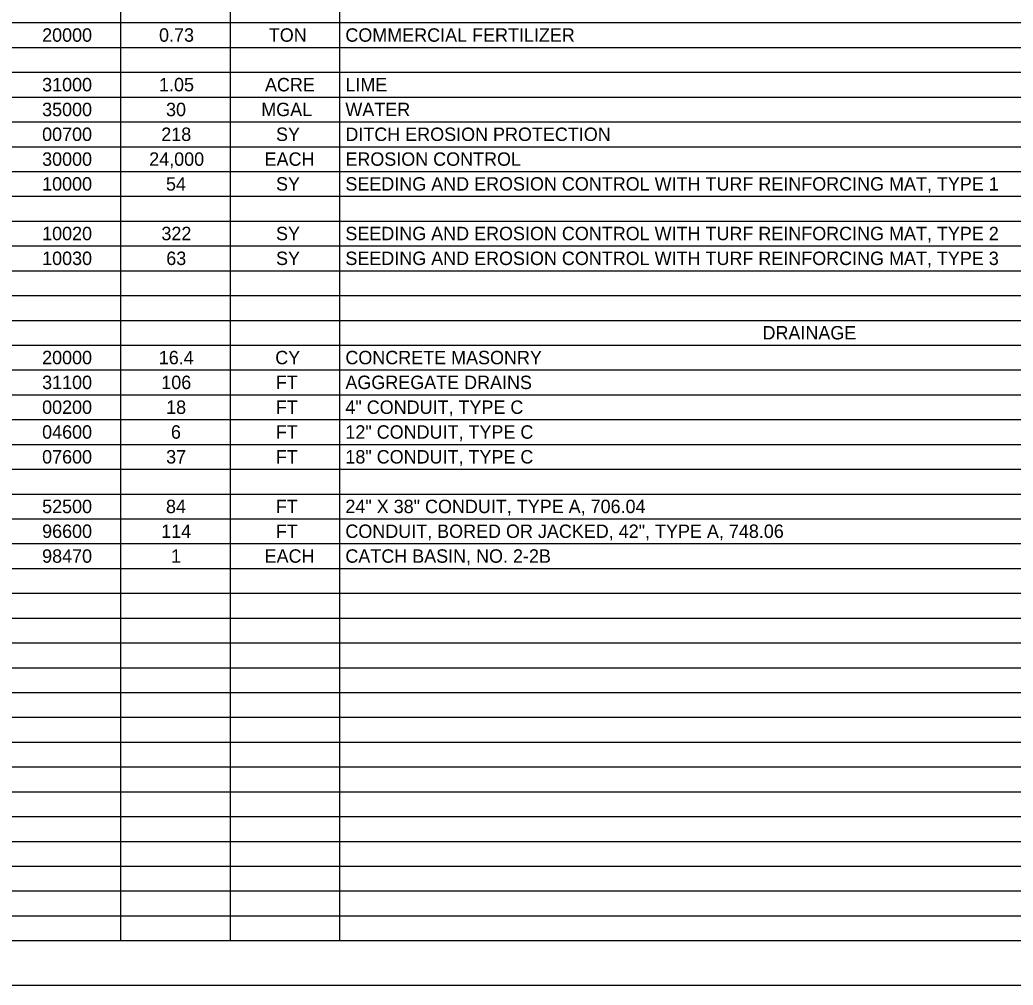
# Model space of a CAD drawing. Extents: x 0 to 1700, y 0 to 1100.
# Drawn here: x 845 to 1405, y 0 to 545 of the extents above; entities that cross this region are included whole.
import ezdxf

# ---------------------------------------------------------------- set-up
doc = ezdxf.new("R2010")
doc.units = 0
for name, color, linetype in [('SH_Border', 7, 'Continuous'), ('SH_Cut_Line', 7, 'Continuous'), ('SH_Text', 7, 'Continuous')]:
    doc.layers.add(name, color=color, linetype=linetype)

msp = doc.modelspace()

# ---------------------------------------------------------------- linework, layer by layer
at = {"layer": 'SH_Border'}
msp.add_lwpolyline([(75, 1075), (1675, 1075), (1675, 25), (75, 25)], close=True, dxfattribs=at)
at = {"layer": 'SH_Cut_Line'}
msp.add_lwpolyline([(0, 0), (1700, 0), (1700, 1100), (0, 1100)], close=True, dxfattribs=at)
at = {"layer": 'SH_Text'}
for p, q in [((901.73, 1075), (901.73, 25.12)), ((963.49, 1075), (963.49, 25.12)), ((1025.24, 1075), (1025.24, 25.12)), ((75, 543.06), (1600, 543.06)), ((75, 529.06), (1600, 529.06)), ((75, 515.06), (1600, 515.06)), ((75, 501.07), (1600, 501.07)), ((75, 487.07), (1600, 487.07)), ((75, 473.07), (1600, 473.07)), ((75, 459.07), (1600, 459.07)), ((75, 445.07), (1600, 445.07)), ((75, 431.07), (1600, 431.07)), ((75, 417.08), (1600, 417.08)), ((75, 403.08), (1600, 403.08)), ((75, 389.08), (1600, 389.08)), ((75, 375.08), (1600, 375.08)), ((75, 361.08), (1600, 361.08)), ((75, 347.08), (1600, 347.08)), ((75, 333.09), (1600, 333.09)), ((75, 319.09), (1600, 319.09)), ((75, 305.09), (1600, 305.09)), ((75, 291.09), (1600, 291.09)), ((75, 277.09), (1600, 277.09)), ((75, 263.09), (1600, 263.09)), ((75, 249.1), (1600, 249.1)), ((75, 235.1), (1600, 235.1)), ((75, 221.1), (1600, 221.1)), ((75, 207.1), (1600, 207.1)), ((75, 193.1), (1600, 193.1)), ((75, 179.1), (1600, 179.1)), ((75, 165.11), (1600, 165.11)), ((75, 151.11), (1600, 151.11)), ((75, 137.11), (1600, 137.11)), ((75, 123.11), (1600, 123.11)), ((75, 109.11), (1600, 109.11)), ((75, 95.11), (1600, 95.11)), ((75, 81.12), (1600, 81.12)), ((75, 67.12), (1600, 67.12)), ((75, 53.12), (1600, 53.12)), ((75, 39.12), (1600, 39.12)), ((75, 25.12), (1600, 25.12))]:
    msp.add_line(p, q, dxfattribs=at)

# ---------------------------------------------------------------- texts
for s, height, p in [('20000', 7.576, (857.43, 532.27)), ('0.73', 7.576, (923.41, 532.27)), ('TON', 7.576, (985.33, 532.27)), ('COMMERCIAL FERTILIZER', 7.5756, (1028.54, 532.27)), ('31000', 7.576, (857.43, 504.28)), ('1.05', 7.576, (923.4, 504.28)), ('ACRE', 7.576, (983.17, 504.28)), ('LIME', 7.576, (1028.54, 504.28)), ('35000', 7.576, (857.43, 490.28)), ('30', 7.576, (927.35, 490.28)), ('MGAL', 7.576, (981.06, 490.28)), ('WATER', 7.576, (1028.54, 490.28)), ('00700', 7.576, (857.43, 476.28)), ('218', 7.576, (924.67, 476.28)), ('SY', 7.576, (989.41, 476.28)), ('DITCH EROSION PROTECTION', 7.5756, (1028.54, 476.28)), ('30000', 7.576, (857.43, 462.28)), ('24,000', 7.576, (917.85, 462.28)), ('EACH', 7.576, (982.97, 462.28)), ('EROSION CONTROL', 7.5756, (1028.54, 462.28)), ('10000', 7.576, (857.43, 448.28)), ('54', 7.576, (927.32, 448.28)), ('SY', 7.576, (989.41, 448.28)), ('SEEDING AND EROSION CONTROL WITH TURF REINFORCING MAT, TYPE 1', 7.5756, (1028.54, 448.28)), ('10020', 7.576, (857.43, 420.29)), ('322', 7.576, (924.74, 420.29)), ('SY', 7.576, (989.41, 420.29)), ('SEEDING AND EROSION CONTROL WITH TURF REINFORCING MAT, TYPE 2', 7.5756, (1028.54, 420.29)), ('10030', 7.576, (857.43, 406.29)), ('63', 7.576, (927.49, 406.29)), ('SY', 7.576, (989.41, 406.29)), ('SEEDING AND EROSION CONTROL WITH TURF REINFORCING MAT, TYPE 3', 7.5756, (1028.54, 406.29)), ('DRAINAGE', 7.576, (1263.88, 364.29)), ('20000', 7.576, (857.43, 350.3)), ('16.4', 7.576, (923.24, 350.3)), ('CY', 7.576, (988.96, 350.3)), ('CONCRETE MASONRY', 7.5756, (1028.54, 350.3)), ('31100', 7.576, (857.43, 336.3)), ('106', 7.576, (924.66, 336.3)), ('FT', 7.576, (989.32, 336.3)), ('AGGREGATE DRAINS', 7.5756, (1028.54, 336.3)), ('00200', 7.576, (857.43, 322.3)), ('18', 7.576, (927.39, 322.3)), ('FT', 7.576, (989.32, 322.3)), ('4" CONDUIT, TYPE C', 7.5756, (1028.54, 322.3)), ('04600', 7.576, (857.43, 308.3)), ('6', 7.58, (930.1, 308.3)), ('FT', 7.576, (989.32, 308.3)), ('12" CONDUIT, TYPE C', 7.5756, (1028.54, 308.3)), ('07600', 7.576, (857.43, 294.3)), ('37', 7.576, (927.41, 294.3)), ('FT', 7.576, (989.32, 294.3)), ('18" CONDUIT, TYPE C', 7.5756, (1028.54, 294.3)), ('52500', 7.576, (857.43, 266.31)), ('84', 7.576, (927.32, 266.31)), ('FT', 7.576, (989.32, 266.31)), ('24" X 38" CONDUIT, TYPE A, 706.04', 7.5756, (1028.54, 266.31)), ('96600', 7.576, (857.43, 252.31)), ('114', 7.576, (924.6, 252.31)), ('FT', 7.576, (989.32, 252.31)), ('CONDUIT, BORED OR JACKED, 42", TYPE A, 748.06', 7.5756, (1028.54, 252.31)), ('98470', 7.576, (857.43, 238.31)), ('1', 7.58, (930.18, 238.31)), ('EACH', 7.576, (982.97, 238.31)), ('CATCH BASIN, NO. 2-2B', 7.5756, (1028.54, 238.31))]:
    msp.add_text(s, height=height, dxfattribs=at).set_placement(p)

doc.saveas('drawing.dxf')
